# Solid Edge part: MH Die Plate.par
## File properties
Author: Dave
Template: Normal.par
Last saved by: Dave
Revision: 16
Application: Solid Edge
Accuracy: 0.990
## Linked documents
Squared Leg Foot.par
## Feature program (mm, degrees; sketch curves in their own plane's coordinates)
sketch for "unnamed Protrusion 1" plane through (0, 0, 0) normal (0, 0, 1) x-axis (1, 0, 0)
  line (-87.5, -87.5) -> (87.5, -87.5)
  line (87.5, -87.5) -> (87.5, 87.5)
  line (87.5, 87.5) -> (-87.5, 87.5)
  line (-87.5, 87.5) -> (-87.5, -87.5)
  dimension (linear) = 87.5
  dimension (linear) = 87.5
extrude "unnamed Protrusion 1" add finite 36 along -normal
sketch for "Hole_1" plane through (0, 0, -36) normal (0, 0, -1) x-axis (-1, 0, 0)
  hole centre (0, 0) bore radius 7
hole "Hole_1" diameter 14 through  VBottomAngle = 118 deg
boolean "unnamed Boolean 1"
sketch for "unnamed Cutout 1" plane through (0, 0, 0) normal (0, 0, 1) x-axis (1, 0, 0)
  line (-29.4454, 58.2476) -> (-29.4454, 12.7988)
  line (-29.4454, 12.7988) -> (29.4362, 12.7988)
  line (29.4362, 12.7988) -> (29.4362, 71.6804)
  line (29.4362, 71.6804) -> (-16.0126, 71.6804)
  line (-16.0126, 71.6804) -> (-29.4454, 58.2476)
extrude "unnamed Cutout 1" cut through along -normal
sketch for "Hole_10" plane through (0, 0, -36) normal (0, 0, -1) x-axis (-1, 0, 0)
  hole centre (70, 70) bore radius 10
hole "Hole_10" diameter 20 through  CounterBoreDepth = 4 mm; VBottomAngle = 118 deg
sketch for "unnamed Hole 1" plane through (0, 0, -36) normal (0, 0, -1) x-axis (-1, 0, 0)
  hole centre (70, -70) bore radius 10
hole "unnamed Hole 1" through
sketch for "unnamed Hole 2" plane through (0, 0, -36) normal (0, 0, -1) x-axis (-1, 0, 0)
  hole centre (-70, -70) bore radius 10
hole "unnamed Hole 2" through
sketch for "unnamed Hole 3" plane through (0, 0, -36) normal (0, 0, -1) x-axis (-1, 0, 0)
  hole centre (-70, 70) bore radius 10
hole "unnamed Hole 3" through
sketch for "Hole_14" plane through (0, 0, -36) normal (0, 0, -1) x-axis (1, 0, 0)
  hole centre (74.5, 45) bore radius 4.188
hole "Hole_14" finite  VBottomAngle = 118 deg
sketch for "unnamed Hole 4" plane through (0, 0, -36) normal (0, 0, -1) x-axis (1, 0, 0)
  hole centre (74.5, -45) bore radius 4.188
hole "unnamed Hole 4" finite
sketch for "unnamed Hole 5" plane through (0, 0, -36) normal (0, 0, -1) x-axis (1, 0, 0)
  hole centre (-74.5, -45) bore radius 4.188
hole "unnamed Hole 5" finite
sketch for "unnamed Hole 6" plane through (0, 0, -36) normal (0, 0, -1) x-axis (1, 0, 0)
hole "unnamed Hole 6" finite
sketch for "Hole_18" plane through (0, 0, -36) normal (0, 0, -1) x-axis (-1, 0, 0)
hole "Hole_18" diameter 10 through  VBottomAngle = 118 deg
sketch for "unnamed Hole 7" plane through (0, 0, -36) normal (0, 0, -1) x-axis (-1, 0, 0)
  hole centre (50, 60) bore radius 5
hole "unnamed Hole 7" through
sketch for "unnamed Hole 8" plane through (0, 0, -36) normal (0, 0, -1) x-axis (-1, 0, 0)
  hole centre (50, -63.75) bore radius 5
hole "unnamed Hole 8" through
sketch for "unnamed Hole 9" plane through (0, 0, -36) normal (0, 0, -1) x-axis (-1, 0, 0)
hole "unnamed Hole 9" through
pattern "unnamed Pattern 1" of "Hole_10", "unnamed Hole 1", "unnamed Hole 2", "unnamed Hole 3"
pattern "unnamed Pattern 2" of "Hole_14", "unnamed Hole 4", "unnamed Hole 5", "unnamed Hole 6"
pattern "unnamed Pattern 3" of "Hole_18", "unnamed Hole 7", "unnamed Hole 8", "unnamed Hole 9"
Other named dimensions: "CoordinateSystem_1": X_Translation = -3.765 mm; Y_Translation = 46 mm; Z_Translation = -9.58 mm | "CopyConstruction_1": XScale = 1.008; YScale = 1.008; ZScale = 1.008
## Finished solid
Body 1: solid body, 252 faces, 528 edges, 282 vertices.
  Faces by surface: cylinder 102, spline 48, plane 43, sphere 38, torus 16, cone 5
  Edges by curve: line 200, circle 168, curve on surface 124, ellipse 26, spline 10
Body 2: solid body, 82 faces, 165 edges, 76 vertices.
  Faces by surface: cylinder 40, plane 24, sphere 10, cone 4, spline 2, torus 2
  Edges by curve: line 77, circle 76, curve on surface 6, ellipse 6
Bounding box of the edges (mm; curved faces can reach further): 175.000 x 175.000 x 61.700, from (-87.5, -87.5, -36) to (87.5, 87.5, 25.7).
Cylindrical faces by radius (mm): R0.504 x118, R1.008 x5, R4.188 x4, R4.2235 x1, R5 x4, R7 x1, R7.2475 x1, R10 x4, R12 x4
Conical faces (half-angle, radius in mm at the cone's reference point): 1 deg R7.056 x1, 1 deg R20.412 x1, 1 deg R23.436 x3, 59 deg R4.188 x4
Toroidal faces (ring radius, tube radius in mm): R0.504 r0.504 x5, R1.512 r0.504 x1, R6.1209 r0.504 x1, R6.7435 r0.504 x1, R7.5513 r0.504 x1, R7.7515 r0.504 x1, R19.9167 r0.504 x1, R21.1184 r0.504 x1, R22.7296 r0.504 x3, R23.9313 r0.504 x3
Spherical faces by radius (mm): R0.504 x48
Planar faces by outward normal: +x 5, +y 4, +z 6, -x 4, -y 5, -z 12, oblique 31
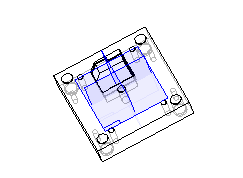
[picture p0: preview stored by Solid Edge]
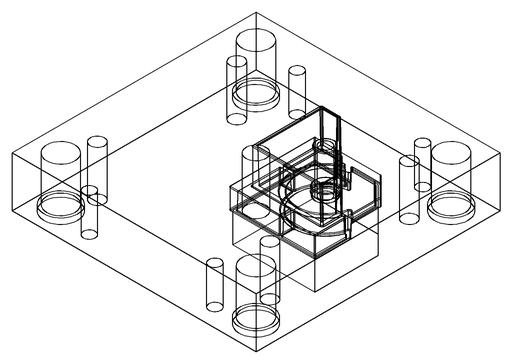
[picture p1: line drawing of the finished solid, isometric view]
